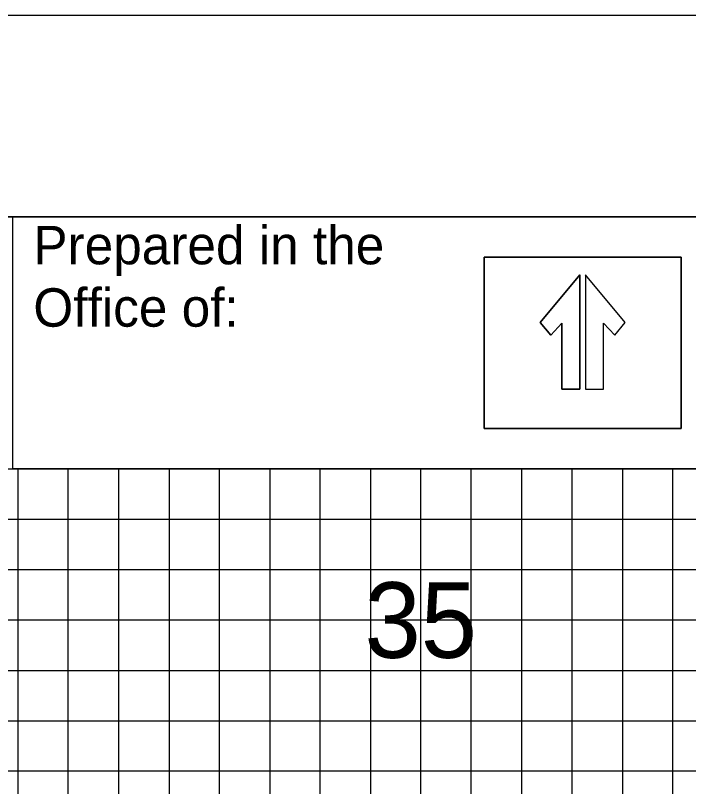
# Model space of a CAD drawing. Extents: x -7 to 162, y -2 to 217.
# Drawn here: x 110.98 to 117.66, y 209.35 to 217 of the extents above; entities that cross this region are included whole.
import ezdxf

# ---------------------------------------------------------------- set-up
doc = ezdxf.new("R2010")
doc.units = 0
for name, color, linetype in [('Exist Cross Section Cell', 7, 'Continuous'), ('Prop CMT Pvmt Course 2', 7, 'Continuous'), ('Prop CMT Pvmt Course 2 Wedge', 7, 'Continuous'), ('Prop CMT Pvmt Course 3', 7, 'Continuous'), ('Prop CMT Pvmt Surface', 7, 'Continuous'), ('Prop CMT Shld Paved Course 1', 7, 'Continuous'), ('Prop CMT Shld Paved Course 2', 7, 'Continuous'), ('Prop CMT Shld Paved Course 3', 7, 'Continuous'), ('Prop CMT Subgrade Earthwork', 7, 'Continuous'), ('Prop XS Side Slope Text', 7, 'Continuous'), ('Scratch_Level_3', 7, 'Continuous')]:
    doc.layers.add(name, color=color, linetype=linetype)

msp = doc.modelspace()

# ---------------------------------------------------------------- linework, layer by layer
at = {"layer": 'Prop CMT Pvmt Course 2'}
msp.add_line((0, 212), (160, 212), dxfattribs=at)
for points in [[(0, 211.5), (135, 211.5), (160, 211.5)], [(160, 211), (0, 211)], [(0, 210.5), (160, 210.5)], [(160, 209.5), (0, 209.5)]]:
    msp.add_lwpolyline(points, dxfattribs=at)
at = {"layer": 'Prop CMT Pvmt Course 3'}
for p, q in [((115, 215), (110, 215)), ((115, 110), (115, 212.5))]:
    msp.add_line(p, q, dxfattribs=at)
msp.add_lwpolyline([(0, 210), (160, 210)], dxfattribs=at)
at = {"layer": 'Prop CMT Pvmt Surface'}
msp.add_lwpolyline([(110.9512, 215), (130, 215), (130, 212.5), (110.9512, 212.5)], close=True, dxfattribs=at)
at = {"layer": 'Prop CMT Shld Paved Course 1'}
msp.add_lwpolyline([(-6.7, 107.5), (161.65, 107.5), (161.65, 217), (-6.7, 217)], close=True, dxfattribs=at)
at = {"layer": 'Prop CMT Shld Paved Course 2'}
msp.add_lwpolyline([(-5.4, 109.5), (161.2, 109.5), (161.2, 215), (-5.4, 215)], close=True, dxfattribs=at)
at = {"layer": 'Prop CMT Shld Paved Course 3'}
for points in [[(72.5, 110), (77.5, 110), (77.5, 215), (82.5, 215), (82.5, 110), (87.5, 110), (87.5, 215), (92.5, 215), (92.5, 110), (97.5, 110), (97.5, 215), (102.5, 215), (102.5, 110), (107.5, 110), (107.5, 215), (112.5, 215)], [(117.5, 215), (122.5, 215)], [(0, 212.5), (137.5, 212.5)], [(112.5, 212.5), (112.5, 110), (117.5, 110), (117.5, 212.5)]]:
    msp.add_lwpolyline(points, dxfattribs=at)
at = {"layer": 'Prop CMT Subgrade Earthwork'}
for points in [[(110, 110), (110.5, 110), (110.5, 215), (111, 215)], [(111.5, 215), (112, 215)], [(113, 215), (113.5, 215)], [(114, 215), (114.5, 215)], [(115.5, 215), (116, 215)], [(116.5, 215), (117, 215)], [(111, 212.5), (111, 110)], [(111, 110), (111.5, 110), (111.5, 212.5)], [(112, 212.5), (112, 110)], [(112.5, 110), (113, 110), (113, 212.5)], [(113.5, 212.5), (113.5, 110)], [(113.5, 110), (114, 110), (114, 212.5)], [(114.5, 212.5), (114.5, 110)], [(115, 110), (115.5, 110), (115.5, 212.5)], [(116, 212.5), (116, 110)], [(116, 110), (116.5, 110), (116.5, 212.5)], [(117, 212.5), (117, 110)]]:
    msp.add_lwpolyline(points, dxfattribs=at)
at = {"layer": 'Prop XS Side Slope Text'}
for points in [[(117.584, 214.5995), (115.6266, 214.5995), (115.6266, 212.9005), (117.584, 212.9005), (117.584, 214.5995)], [(116.5788, 214.4257), (116.5788, 213.2897), (116.3999, 213.2897), (116.3999, 213.945), (116.2891, 213.8276), (116.1849, 213.9521), (116.5788, 214.4257)], [(116.1849, 213.9521), (116.2891, 213.8276), (116.3999, 213.945), (116.3999, 213.2897), (116.5788, 213.2897), (116.5788, 214.4257), (116.1849, 213.9521)], [(116.6339, 214.4257), (116.6339, 213.2897), (116.8129, 213.2897), (116.8129, 213.945), (116.9237, 213.8276), (117.0279, 213.9521), (116.6339, 214.4257)]]:
    msp.add_lwpolyline(points, dxfattribs=at)
for points in [[(115.6266, 214.5995), (117.584, 214.5995), (117.584, 212.9005), (115.6266, 212.9005)], [(116.6339, 214.4257), (116.6339, 213.2897), (116.8129, 213.2897), (116.8129, 213.945), (116.9237, 213.8276), (117.0279, 213.9521)]]:
    msp.add_lwpolyline(points, close=True, dxfattribs=at)
at = {"layer": 'Scratch_Level_3'}
msp.add_lwpolyline([(160, 215), (0, 215), (0, 110), (160, 110)], close=True, dxfattribs=at)

# ---------------------------------------------------------------- texts
at = {"layer": 'Exist Cross Section Cell'}
msp.add_text('35', height=0.75, dxfattribs=at).set_placement((114.4408, 210.625))
at = {"layer": 'Prop CMT Pvmt Course 2 Wedge'}
for s, height, p in [('Prepared in the ', 0.380976, (111.1533, 214.5302)), ('Office of:', 0.38098, (111.1533, 213.9112))]:
    msp.add_text(s, height=height, rotation=360, dxfattribs=at).set_placement(p)

doc.saveas('drawing.dxf')
